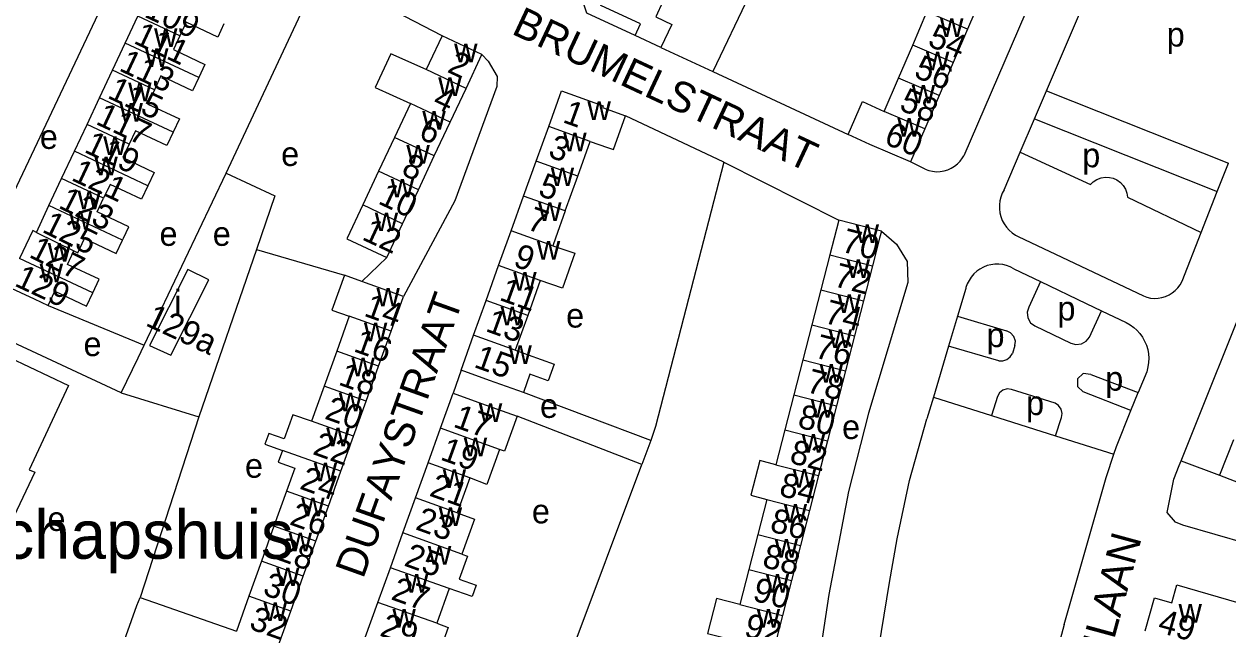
# Model space of a CAD drawing. Extents: x 159045 to 160918, y 380454 to 382516.
# Drawn here: x 160089.8 to 160288.7, y 381185.5 to 381285.4 of the extents above; entities that cross this region are included whole.
import ezdxf

# ---------------------------------------------------------------- set-up
doc = ezdxf.new("R2010")
doc.units = 0
for name, color, linetype in [('BLT_Basislijn', 7, 'Continuous'), ('BLT_Bebouwing', 7, 'Continuous'), ('BLT_Bebouwing_beschrifting', 7, 'Continuous'), ('BLT_Centroide', 7, 'Continuous'), ('BLT_Huisnummer', 7, 'Continuous'), ('BLT_Huisnummer_ tussenligend', 7, 'Continuous'), ('BLT_Onderverdeling_panden', 7, 'Continuous'), ('BLT_Straatnaam', 7, 'Continuous')]:
    doc.layers.add(name, color=color, linetype=linetype)

msp = doc.modelspace()

# ---------------------------------------------------------------- linework, layer by layer
at = {"layer": 'BLT_Basislijn'}
for p, q in [((160263.72, 381306.96), (160245.07, 381263.61)), ((160123.21, 381260.74), (160138.75, 381293.92)), ((160158.88, 381283.41), (160138.75, 381293.92)), ((160258.7, 381274.33), (160266.79, 381293.2)), ((160195.03, 381281.48), (160203.6, 381277.5)), ((160203.6, 381277.5), (160225.95, 381267.13)), ((160256.73, 381269.73), (160258.7, 381274.33)), ((160258.7, 381274.33), (160288.75, 381262.37)), ((160205.39, 381262.57), (160189.18, 381270.21)), ((160254.38, 381264.23), (160256.73, 381269.73)), ((160256.73, 381269.73), (160286.92, 381257.72)), ((160280.94, 381213.21), (160301.87, 381265.58)), ((160251.7, 381257.99), (160254.38, 381264.23)), ((160205.39, 381262.57), (160224.4, 381252.99)), ((160238.67, 381261.38), (160236.26, 381262.58)), ((160286.92, 381257.72), (160288.75, 381262.37)), ((160109.65, 381232.33), (160123.21, 381260.74)), ((160284.26, 381250.96), (160286.92, 381257.72)), ((160254.04, 381250.26), (160274.71, 381240.45)), ((160281.09, 381242.92), (160284.26, 381250.96)), ((160128.23, 381248.12), (160118.69, 381220.46)), ((160128.23, 381248.12), (160142.75, 381243.89)), ((160149.74, 381246.8), (160145.61, 381242.86)), ((160253.32, 381244.96), (160257.74, 381242.83)), ((160245.36, 381241.66), (160244, 381237.11)), ((160257.74, 381242.83), (160255.8, 381238.6)), ((160257.74, 381242.83), (160265.25, 381239.23)), ((160093.82, 381238.87), (160109.65, 381232.33)), ((160265.25, 381239.23), (160267.8, 381237.98)), ((160265.79, 381233.65), (160267.8, 381237.98)), ((160267.8, 381237.98), (160271.88, 381236.05)), ((160105.85, 381224.47), (160078.47, 381237.17)), ((160244, 381237.11), (160242.53, 381232.18)), ((160244, 381237.11), (160252.09, 381234.67)), ((160256.79, 381235.52), (160262.75, 381232.67)), ((160242.53, 381232.18), (160240.03, 381223.75)), ((160250.82, 381229.75), (160242.53, 381232.18)), ((160253.5, 381232.25), (160253.11, 381230.94)), ((160162, 381228.2), (160160.69, 381224.41)), ((160275.26, 381227.94), (160273.84, 381224.49)), ((160266.05, 381227.5), (160273.84, 381224.49)), ((160105.85, 381224.47), (160118.69, 381220.46)), ((160193.33, 381216.6), (160172.3, 381224.5)), ((160240.03, 381223.75), (160238.96, 381220.17)), ((160240.03, 381223.75), (160249.61, 381220.72)), ((160250.6, 381223.83), (160249.61, 381220.72)), ((160260.16, 381222.72), (160252.9, 381225)), ((160272.62, 381221.54), (160264.74, 381224.64)), ((160272.62, 381221.54), (160273.84, 381224.49)), ((160118.69, 381220.46), (160109.03, 381190.62)), ((160191.86, 381212.6), (160171.27, 381220.6)), ((160249.61, 381220.72), (160260.21, 381217.36)), ((160260.21, 381217.36), (160261.17, 381220.4)), ((160193.33, 381216.6), (160191.86, 381212.6)), ((160260.21, 381217.36), (160269.83, 381214.31)), ((160174.48, 381166.13), (160191.86, 381212.6)), ((160280.94, 381213.21), (160287.29, 381210.87)), ((160261.65, 381186.17), (160268.57, 381210.49)), ((160109.03, 381190.62), (160124.89, 381185.09))]:
    msp.add_line(p, q, dxfattribs=at)
for points in [[(160222.72, 381318.67), (160221.61, 381315.23), (160203.6, 381277.5)], [(160116.55, 381305.15), (160111.63, 381307.38), (160081.39, 381243.37)], [(160190.74, 381283.49), (160182.8, 381287.17), (160182.15, 381288.99), (160184.44, 381294.05), (160185.83, 381293.43)], [(160165.46, 381280.32), (160166.51, 381279.22), (160167.97, 381276.71), (160167.94, 381275.05), (160160.97, 381256.17), (160152.52, 381240.38)], [(160238.67, 381261.38), (160239.27, 381261.17), (160239.89, 381261.04), (160240.53, 381260.98), (160241.16, 381261.01), (160241.79, 381261.11), (160242.4, 381261.3), (160242.98, 381261.55), (160243.52, 381261.88), (160244.02, 381262.28), (160244.46, 381262.73), (160244.85, 381263.24), (160245.07, 381263.61)], [(160254.38, 381264.23), (160265.98, 381258.86), (160266.41, 381259.28), (160267, 381259.68), (160267.71, 381259.96), (160268.43, 381260.07), (160269.09, 381260.04), (160269.73, 381259.89), (160270.33, 381259.62), (160270.91, 381259.2), (160271.39, 381258.68), (160271.75, 381258.07), (160271.97, 381257.43), (160272.06, 381256.79), (160284.26, 381250.96)], [(160205.39, 381262.57), (160194.13, 381218.88), (160193.33, 381216.6)], [(160123.21, 381260.74), (160131.26, 381257.01), (160128.23, 381248.12)], [(160251.7, 381257.99), (160251.4, 381257.41), (160251.16, 381256.79), (160251.01, 381256.15), (160250.93, 381255.5), (160250.93, 381254.84), (160251.01, 381254.19), (160251.17, 381253.55), (160251.4, 381252.93), (160251.71, 381252.35), (160252.09, 381251.81), (160252.52, 381251.32), (160253.02, 381250.89), (160253.56, 381250.52), (160254.04, 381250.26)], [(160231.44, 381251.18), (160233.95, 381249), (160235.7, 381246.13), (160235.81, 381242.7), (160229.31, 381221.08), (160226.02, 381208.16), (160222.77, 381191.13), (160220.43, 381175.9)], [(160253.32, 381244.96), (160252.73, 381245.26), (160252.12, 381245.49), (160251.48, 381245.64), (160250.83, 381245.71), (160250.18, 381245.71), (160249.53, 381245.62), (160248.9, 381245.46), (160248.29, 381245.21), (160247.71, 381244.9), (160247.18, 381244.52), (160246.7, 381244.08), (160246.27, 381243.58), (160245.91, 381243.03), (160245.62, 381242.45), (160245.4, 381241.83), (160245.36, 381241.66)], [(160274.71, 381240.45), (160275.3, 381240.24), (160275.91, 381240.11), (160276.53, 381240.05), (160277.16, 381240.08), (160277.77, 381240.18), (160278.37, 381240.37), (160278.94, 381240.62), (160279.47, 381240.95), (160279.96, 381241.35), (160280.39, 381241.8), (160280.76, 381242.3), (160281.09, 381242.92)], [(160255.8, 381238.6), (160255.53, 381237.78), (160255.62, 381236.85), (160256.09, 381236.03), (160256.79, 381235.52)], [(160271.88, 381236.05), (160272.52, 381235.7), (160273.11, 381235.27), (160273.65, 381234.78), (160274.14, 381234.24), (160274.57, 381233.64), (160274.92, 381233.01), (160275.21, 381232.33), (160275.42, 381231.63), (160275.55, 381230.91), (160275.61, 381230.18), (160275.58, 381229.46), (160275.47, 381228.73), (160275.26, 381227.94)], [(160253.5, 381232.25), (160253.56, 381232.99), (160253.31, 381233.76), (160252.77, 381234.36), (160252.09, 381234.67)], [(160262.75, 381232.67), (160263.56, 381232.46), (160264.46, 381232.57), (160265.25, 381233), (160265.79, 381233.65)], [(160105.85, 381224.47), (160108.65, 381230.24), (160109.65, 381232.33)], [(160250.82, 381229.75), (160251.49, 381229.74), (160252.17, 381229.96), (160252.73, 381230.39), (160253.11, 381230.94)], [(160266.05, 381227.5), (160264.78, 381227.64), (160263.83, 381226.79), (160263.81, 381225.52), (160264.74, 381224.64)], [(160252.9, 381225), (160252.22, 381225.09), (160251.51, 381224.89), (160250.93, 381224.43), (160250.6, 381223.83)], [(160261.17, 381220.4), (160261.27, 381221.06), (160261.11, 381221.75), (160260.71, 381222.34), (160260.16, 381222.72)], [(160232.78, 381193.15), (160234.04, 381200.35), (160236.1, 381209.96), (160238.96, 381220.17)], [(160269.83, 381214.31), (160270.25, 381215.58), (160272.62, 381221.54)], [(160268.57, 381210.49), (160268.61, 381210.64), (160269.83, 381214.31)], [(160347.04, 381193.19), (160346.77, 381192.26), (160345.84, 381188.3), (160345.36, 381187.39), (160343.35, 381185.68), (160339.97, 381185.65), (160281.2, 381202.61), (160280.02, 381203.09), (160278.65, 381204.68), (160279.73, 381210.18), (160280.63, 381212.43), (160280.94, 381213.21)], [(160227.8, 381161.01), (160229.62, 381173.91), (160232.78, 381193.15)], [(160105.84, 381174.41), (160103.46, 381175.25), (160108.45, 381189.33), (160109.03, 381190.62)], [(160261.65, 381186.17), (160256.59, 381167.34), (160253.29, 381154.15)]]:
    msp.add_lwpolyline(points, dxfattribs=at)
at = {"layer": 'BLT_Bebouwing'}
for p, q in [((160248.01, 381289.99), (160245.66, 381284.51)), ((160236.61, 381281.9), (160238.96, 381287.38)), ((160106.55, 381282.23), (160108.63, 381286.66)), ((160165.46, 381280.32), (160158.88, 381283.41)), ((160195.03, 381281.48), (160190.74, 381283.49)), ((160245.66, 381284.51), (160243.31, 381279.03)), ((160104.43, 381277.73), (160106.55, 381282.23)), ((160234.25, 381276.42), (160236.61, 381281.9)), ((160162.84, 381274.74), (160165.46, 381280.32)), ((160102.31, 381273.2), (160104.43, 381277.73)), ((160243.31, 381279.03), (160240.96, 381273.54)), ((160231.9, 381270.94), (160234.25, 381276.42)), ((160160.22, 381269.15), (160162.84, 381274.74)), ((160240.96, 381273.54), (160238.61, 381268.06)), ((160100.23, 381268.79), (160102.31, 381273.2)), ((160153.63, 381272.24), (160151.01, 381266.65)), ((160098.15, 381264.35), (160100.23, 381268.79)), ((160157.59, 381263.57), (160160.22, 381269.15)), ((160174.41, 381262.71), (160176.48, 381268.46)), ((160238.61, 381268.06), (160236.26, 381262.58)), ((160151.01, 381266.65), (160148.39, 381261.07)), ((160181.29, 381260.24), (160183.35, 381265.99)), ((160229.55, 381265.46), (160225.95, 381267.13)), ((160236.26, 381262.58), (160229.55, 381265.46)), ((160096.03, 381259.85), (160098.15, 381264.35)), ((160154.97, 381257.98), (160157.59, 381263.57)), ((160172.34, 381256.96), (160174.41, 381262.71)), ((160093.93, 381255.37), (160096.03, 381259.85)), ((160148.39, 381261.07), (160145.77, 381255.48)), ((160179.22, 381254.49), (160181.29, 381260.24)), ((160152.35, 381252.39), (160154.97, 381257.98)), ((160170.27, 381251.21), (160172.34, 381256.96)), ((160091.86, 381250.96), (160093.93, 381255.37)), ((160231.44, 381251.18), (160224.4, 381252.99)), ((160222.92, 381247.22), (160221.43, 381241.45)), ((160116.87, 381244.84), (160110.52, 381232.26)), ((160166.14, 381239.7), (160168.21, 381245.46)), ((160229.95, 381245.41), (160228.47, 381239.64)), ((160152.52, 381240.38), (160145.61, 381242.86)), ((160175.08, 381242.98), (160173.02, 381237.23)), ((160150.45, 381234.61), (160152.52, 381240.38)), ((160164.07, 381233.95), (160166.14, 381239.7)), ((160221.43, 381241.45), (160219.95, 381235.68)), ((160228.47, 381239.64), (160226.98, 381233.86)), ((160143.54, 381237.09), (160141.47, 381231.31)), ((160173.02, 381237.23), (160170.95, 381231.48)), ((160219.95, 381235.68), (160218.46, 381229.9)), ((160148.38, 381228.83), (160150.45, 381234.61)), ((160162, 381228.2), (160164.07, 381233.95)), ((160226.98, 381233.86), (160225.5, 381228.09)), ((160141.47, 381231.31), (160139.4, 381225.53)), ((160218.46, 381229.9), (160216.98, 381224.13)), ((160146.31, 381223.05), (160148.38, 381228.83)), ((160225.5, 381228.09), (160224.01, 381222.32)), ((160139.4, 381225.53), (160137.32, 381219.76)), ((160158.62, 381218.64), (160160.69, 381224.41)), ((160216.98, 381224.13), (160215.49, 381218.36)), ((160144.24, 381217.28), (160146.31, 381223.05)), ((160224.01, 381222.32), (160222.53, 381216.55)), ((160156.55, 381212.87), (160158.62, 381218.64)), ((160215.49, 381218.36), (160214.01, 381212.58)), ((160142.16, 381211.5), (160144.24, 381217.28)), ((160222.53, 381216.55), (160221.04, 381210.77)), ((160289.58, 381216.69), (160287.29, 381210.87)), ((160154.47, 381207.11), (160156.55, 381212.87)), ((160140.09, 381205.72), (160142.16, 381211.5)), ((160163.46, 381210.39), (160161.38, 381204.62)), ((160221.04, 381210.77), (160219.56, 381205)), ((160287.29, 381210.87), (160294.59, 381208)), ((160133.18, 381208.2), (160131.1, 381202.43)), ((160152.4, 381201.34), (160154.47, 381207.11)), ((160212.52, 381206.81), (160211.04, 381201.04)), ((160138.02, 381199.95), (160140.09, 381205.72)), ((160219.56, 381205), (160218.07, 381199.23)), ((160131.1, 381202.43), (160129.03, 381196.65)), ((160135.94, 381194.17), (160138.02, 381199.95)), ((160150.33, 381195.57), (160152.4, 381201.34)), ((160211.04, 381201.04), (160209.55, 381195.26)), ((160218.07, 381199.23), (160216.59, 381193.46)), ((160129.03, 381196.65), (160126.96, 381190.87)), ((160133.87, 381188.39), (160135.94, 381194.17)), ((160148.25, 381189.8), (160150.33, 381195.57)), ((160209.55, 381195.26), (160208.07, 381189.49)), ((160160.05, 381192.13), (160157.99, 381186.4)), ((160216.59, 381193.46), (160215.1, 381187.68)), ((160126.96, 381190.87), (160124.89, 381185.09)), ((160131.8, 381182.61), (160133.87, 381188.39)), ((160146.18, 381184.04), (160148.25, 381189.8)), ((160215.1, 381187.68), (160213.02, 381179.58))]:
    msp.add_line(p, q, dxfattribs=at)
for points in [[(160190.74, 381283.49), (160191.63, 381285.4), (160185.1, 381288.45), (160187.14, 381292.82)], [(160194.9, 381289.29), (160195.35, 381289.08), (160194.16, 381286.55), (160196.82, 381285.31), (160195.03, 381281.48)], [(160122.85, 381285.38), (160121.83, 381283.21), (160116.61, 381285.66), (160115.55, 381283.41)], [(160115.55, 381283.41), (160114.49, 381281.16), (160119.7, 381278.71), (160118.67, 381276.53)], [(160158.88, 381283.41), (160156.75, 381278.89), (160156.26, 381277.83)], [(160156.26, 381277.83), (160150.41, 381280.44), (160147.82, 381274.91), (160153.63, 381272.24)], [(160118.67, 381276.53), (160117.65, 381274.35), (160112.44, 381276.8), (160111.35, 381274.48)], [(160111.35, 381274.48), (160110.26, 381272.15), (160115.48, 381269.7), (160114.44, 381267.5)], [(160176.48, 381268.46), (160178.6, 381274.36), (160185.47, 381271.88), (160185.36, 381271.58), (160189.18, 381270.21)], [(160225.95, 381267.13), (160228.29, 381272.58), (160231.9, 381270.94)], [(160183.35, 381265.99), (160186.18, 381264.97), (160187.17, 381264.62), (160189.18, 381270.21)], [(160114.44, 381267.5), (160113.41, 381265.3), (160108.22, 381267.74), (160107.18, 381265.52)], [(160107.18, 381265.52), (160106.14, 381263.31), (160111.34, 381260.87), (160110.29, 381258.65)], [(160110.29, 381258.65), (160109.25, 381256.42), (160104.03, 381258.87), (160102.96, 381256.59)], [(160106.09, 381249.67), (160106.19, 381249.88), (160106.25, 381250), (160107.12, 381251.86), (160101.9, 381254.32), (160102.96, 381256.59)], [(160145.77, 381255.48), (160143.2, 381250), (160143.14, 381249.88), (160149.74, 381246.8)], [(160179.22, 381254.49), (160177.61, 381250), (160177.15, 381248.73)], [(160149.74, 381246.8), (160151.23, 381250), (160152.35, 381252.39)], [(160224.4, 381252.99), (160223.64, 381250), (160222.92, 381247.22)], [(160091.86, 381250.96), (160091.25, 381251.25), (160090.67, 381250), (160089.1, 381246.64)], [(160098.06, 381247.89), (160098.73, 381247.57), (160099.82, 381249.92), (160105.06, 381247.47), (160106.09, 381249.67)], [(160168.21, 381245.46), (160169.84, 381250), (160170.27, 381251.21)], [(160231.44, 381251.18), (160231.13, 381250), (160229.95, 381245.41)], [(160101.19, 381240.99), (160102.23, 381243.22), (160097.02, 381245.66), (160098.06, 381247.89)], [(160177.15, 381248.73), (160180.82, 381247.5), (160178.75, 381241.75), (160175.08, 381242.98)], [(160110.52, 381232.26), (160114.07, 381230.68), (160120.33, 381243.1), (160116.87, 381244.84)], [(160142.75, 381243.89), (160140.68, 381238.11), (160143.54, 381237.09)], [(160145.61, 381242.86), (160142.75, 381243.89)], [(160086.97, 381242.07), (160091.5, 381239.96), (160093.82, 381238.87)], [(160093.82, 381238.87), (160094.91, 381241.22), (160100.15, 381238.77), (160101.19, 381240.99)], [(160170.95, 381231.48), (160177.36, 381229.2), (160176.37, 381226.44), (160173.38, 381227.51), (160172.3, 381224.5)], [(160172.3, 381224.5), (160166.71, 381226.51), (160162, 381228.2)], [(160160.69, 381224.41), (160165.4, 381222.71), (160171.27, 381220.6)], [(160137.32, 381219.76), (160134.24, 381220.82), (160132.81, 381216.85), (160130.26, 381217.76), (160129.62, 381216), (160132.53, 381214.95)], [(160171.27, 381220.6), (160169.19, 381214.81), (160168.36, 381215.09)], [(160132.53, 381214.95), (160131.82, 381212.98), (160134.54, 381212), (160133.18, 381208.2)], [(160168.36, 381215.09), (160166.28, 381209.3), (160163.46, 381210.39)], [(160214.01, 381212.58), (160211.34, 381213.3), (160209.86, 381207.55), (160212.52, 381206.81)], [(160161.38, 381204.62), (160164.23, 381203.61), (160162.15, 381197.83)], [(160162.15, 381197.83), (160163.07, 381197.5), (160161.69, 381193.67), (160164.51, 381192.68), (160163.84, 381190.79), (160160.05, 381192.13)], [(160275, 381185.12), (160276.52, 381190.57), (160279.38, 381189.78), (160280.23, 381192.74), (160290.49, 381189.76)], [(160208.07, 381189.49), (160204.21, 381190.48), (160202.72, 381184.71), (160206.65, 381183.69), (160206.14, 381181.69), (160208.45, 381180.98)], [(160157.99, 381186.4), (160159.89, 381185.71), (160158.66, 381182.31), (160161.84, 381181.17), (160160.99, 381178.78), (160158.83, 381179.55)]]:
    msp.add_lwpolyline(points, dxfattribs=at)
msp.add_lwpolyline([(160084.11, 381231.82), (160097.17, 381225.65), (160090.69, 381211.76), (160091.6, 381211.33), (160088.14, 381204.01), (160087.27, 381204.36), (160080.55, 381190.6), (160067.54, 381196.84), (160069.83, 381201.63), (160072.09, 381200.56), (160076.37, 381209.66), (160073.54, 381211.02), (160076.95, 381218.25), (160079.83, 381216.89), (160084.08, 381225.98), (160081.87, 381227.05)], close=True, dxfattribs=at)
at = {"layer": 'BLT_Onderverdeling_panden'}
for p, q in [((160245.66, 381284.51), (160238.96, 381287.38)), ((160115.55, 381283.41), (160108.63, 381286.66)), ((160118.67, 381276.53), (160106.55, 381282.23)), ((160243.31, 381279.03), (160236.61, 381281.9)), ((160111.35, 381274.48), (160104.43, 381277.73)), ((160162.84, 381274.74), (160156.26, 381277.83)), ((160240.96, 381273.54), (160234.25, 381276.42)), ((160114.44, 381267.5), (160102.31, 381273.2)), ((160160.22, 381269.15), (160153.63, 381272.24)), ((160238.61, 381268.06), (160231.9, 381270.94)), ((160107.18, 381265.52), (160100.23, 381268.79)), ((160183.35, 381265.99), (160176.48, 381268.46)), ((160157.59, 381263.57), (160151.01, 381266.65)), ((160110.29, 381258.65), (160098.15, 381264.35)), ((160181.29, 381260.24), (160174.41, 381262.71)), ((160102.96, 381256.59), (160096.03, 381259.85)), ((160154.97, 381257.98), (160148.39, 381261.07)), ((160179.22, 381254.49), (160172.34, 381256.96)), ((160106.09, 381249.67), (160093.93, 381255.37)), ((160152.35, 381252.39), (160145.77, 381255.48)), ((160091.86, 381250.96), (160098.06, 381247.89)), ((160177.15, 381248.73), (160170.27, 381251.21)), ((160101.19, 381240.99), (160089.1, 381246.64)), ((160222.92, 381247.22), (160229.95, 381245.41)), ((160175.08, 381242.98), (160168.21, 381245.46)), ((160173.02, 381237.23), (160166.14, 381239.7)), ((160221.43, 381241.45), (160228.47, 381239.64)), ((160150.45, 381234.61), (160143.54, 381237.09)), ((160219.95, 381235.68), (160226.98, 381233.86)), ((160170.95, 381231.48), (160164.07, 381233.95)), ((160148.38, 381228.83), (160141.47, 381231.31)), ((160218.46, 381229.9), (160225.5, 381228.09)), ((160146.31, 381223.05), (160139.4, 381225.53)), ((160216.98, 381224.13), (160224.01, 381222.32)), ((160144.24, 381217.28), (160137.32, 381219.76)), ((160168.36, 381215.09), (160158.62, 381218.64)), ((160215.49, 381218.36), (160222.53, 381216.55)), ((160142.16, 381211.5), (160132.53, 381214.95)), ((160163.46, 381210.39), (160156.55, 381212.87)), ((160214.01, 381212.58), (160221.04, 381210.77)), ((160140.09, 381205.72), (160133.18, 381208.2)), ((160161.38, 381204.62), (160154.47, 381207.11)), ((160212.52, 381206.81), (160219.56, 381205)), ((160138.02, 381199.95), (160131.1, 381202.43)), ((160162.15, 381197.83), (160152.4, 381201.34)), ((160211.04, 381201.04), (160218.07, 381199.23)), ((160135.94, 381194.17), (160129.03, 381196.65)), ((160160.05, 381192.13), (160150.33, 381195.57)), ((160209.55, 381195.26), (160216.59, 381193.46)), ((160133.87, 381188.39), (160126.96, 381190.87)), ((160157.99, 381186.4), (160148.25, 381189.8)), ((160208.07, 381189.49), (160215.1, 381187.68))]:
    msp.add_line(p, q, dxfattribs=at)

# ---------------------------------------------------------------- texts
at = {"layer": 'BLT_Bebouwing_beschrifting'}
msp.add_text('Gemeenschapshuis', height=8, dxfattribs=at).set_placement((160039.76, 381197.05))
at = {"layer": 'BLT_Centroide'}
for s, p in [('w', (160241.12, 381283.22)), ('w', (160111.3, 381281.59)), ('p', (160278.56, 381281.65)), ('w', (160160.86, 381279.06)), ('w', (160109.81, 381278.28)), ('w', (160238.78, 381277.72)), ('w', (160107.02, 381272.62)), ('w', (160158.23, 381273.5)), ('w', (160236.44, 381272.25)), ('w', (160105.59, 381269.25)), ('w', (160182.88, 381269.5)), ('w', (160155.61, 381267.91)), ('w', (160234.08, 381266.75)), ('e', (160092.43, 381264.74)), ('w', (160102.91, 381263.72)), ('w', (160178.88, 381264.34)), ('e', (160132.29, 381261.92)), ('w', (160152.98, 381262.31)), ('p', (160264.61, 381261.71)), ('w', (160101.44, 381260.38)), ('w', (160176.82, 381258.59)), ('w', (160150.38, 381256.72)), ('w', (160098.66, 381254.75)), ('w', (160174.74, 381252.84)), ('w', (160097.22, 381251.41)), ('w', (160147.75, 381251.16)), ('e', (160112.2, 381248.73)), ('e', (160120.99, 381248.73)), ('w', (160227.17, 381249.19)), ('w', (160093.73, 381246.12)), ('w', (160174.52, 381246.47)), ('w', (160092.4, 381242.72)), ('w', (160225.69, 381243.44)), ('w', (160170.62, 381241.34)), ('i', (160114.62, 381237.42)), ('w', (160148.03, 381238.72)), ('w', (160224.2, 381237.66)), ('w', (160168.54, 381235.59)), ('e', (160179.36, 381235.23)), ('p', (160260.51, 381236.41)), ('w', (160145.96, 381232.97)), ('e', (160099.65, 381230.52)), ('w', (160222.72, 381231.88)), ('p', (160248.8, 381232)), ('w', (160169.83, 381229.22)), ('w', (160143.89, 381227.19)), ('w', (160221.23, 381226.12)), ('p', (160268.41, 381224.81)), ('w', (160141.81, 381221.41)), ('p', (160255.34, 381220.78)), ('w', (160164.94, 381219.62)), ('e', (160175.05, 381220.31)), ('w', (160219.75, 381220.34)), ('e', (160224.94, 381216.82)), ('w', (160139.74, 381215.62)), ('w', (160162.45, 381213.97)), ('w', (160218.27, 381214.56)), ('e', (160126.32, 381210.43)), ('w', (160137.67, 381209.84)), ('w', (160158.97, 381208.75)), ('w', (160216.78, 381208.78)), ('w', (160135.6, 381204.06)), ('e', (160173.71, 381202.89)), ('w', (160215.3, 381203.03)), ('e', (160093.69, 381201.64)), ('w', (160158.32, 381202.47)), ('w', (160133.52, 381198.28)), ('w', (160213.81, 381197.25)), ('w', (160156.52, 381196.06)), ('w', (160131.45, 381192.53)), ('w', (160152.74, 381191.44)), ('w', (160212.33, 381191.47)), ('w', (160129.38, 381186.75)), ('w', (160150.67, 381185.69)), ('w', (160210.84, 381185.69)), ('w', (160280.51, 381186.5))]:
    msp.add_text(s, height=4, dxfattribs=at).set_placement(p)
at = {"layer": 'BLT_Huisnummer'}
for s, rotation, p in [('54', 336.788, (160238.89, 381281.85)), ('111', 334.83, (160107.75, 381282.27)), ('2', 334.8689, (160159.56, 381277.51)), ('115', 334.8299, (160103.43, 381273.24)), ('1', 340.2259, (160178.63, 381269.19)), ('6', 334.8685, (160154.8, 381266.6)), ('60', 336.788, (160231.68, 381265.69)), ('119', 334.8602, (160099.58, 381264.28)), ('5', 340.2212, (160174.54, 381257.12)), ('123', 333.6163, (160095.34, 381255.09)), ('12', 334.9841, (160145.47, 381249.84)), ('70', 345.5677, (160224.65, 381247.82)), ('9', 340.2259, (160170.44, 381245.44)), ('129', 334.9672, (160088.07, 381242.2)), ('14', 340.2648, (160145.79, 381237.22)), ('74', 345.5677, (160221.81, 381236.05)), ('129a', 335.1307, (160109.72, 381235.64)), ('15', 340.2261, (160163.96, 381228.75)), ('18', 340.2648, (160141.59, 381225.85)), ('78', 345.5677, (160218.86, 381224.63)), ('17', 340.2234, (160160.54, 381218.9)), ('22', 340.2622, (160137.34, 381214.37)), ('82', 345.5677, (160216.09, 381212.93)), ('21', 340.2281, (160156.59, 381207.51)), ('26', 340.2622, (160133.51, 381202.76)), ('86', 345.5677, (160212.85, 381201.6)), ('25', 340.2244, (160152.41, 381195.96)), ('32', 340.2568, (160126.82, 381185.54)), ('92', 345.5802, (160208.58, 381184.24)), ('49', 344.4851, (160276.9, 381184.96))]:
    msp.add_text(s, height=4, rotation=rotation, dxfattribs=at).set_placement(p)
at = {"layer": 'BLT_Huisnummer_ tussenligend'}
for s, rotation, p in [('109', 334.8352, (160109.49, 381286.65)), ('113', 334.83, (160105.34, 381277.75)), ('56', 336.788, (160236.61, 381276.71)), ('4', 334.8689, (160157.12, 381271.8)), ('58', 336.788, (160234.19, 381271.28)), ('117', 334.8299, (160101.49, 381268.92)), ('3', 340.2259, (160176.21, 381263.48)), ('8', 334.8685, (160151.95, 381260.6)), ('121', 334.8602, (160097.45, 381259.64)), ('10', 334.8685, (160148.12, 381255.78)), ('125', 333.6163, (160092.63, 381251.09)), ('7', 340.2212, (160172.67, 381251.55)), ('127', 333.6163, (160090.47, 381246.95)), ('72', 345.5677, (160223.38, 381242.11)), ('11', 340.2259, (160168.16, 381239.83)), ('13', 340.2259, (160165.88, 381234.69)), ('16', 340.2648, (160144.08, 381231.36)), ('76', 345.5677, (160220.24, 381230.33)), ('20', 340.2648, (160139.31, 381220.23)), ('80', 345.5677, (160217.43, 381218.78)), ('19', 340.2234, (160158.41, 381213.47)), ('24', 340.2622, (160135.18, 381208.66)), ('84', 345.5677, (160214.37, 381207.51)), ('23', 340.2281, (160154.31, 381201.95)), ('28', 340.2622, (160131.23, 381197.04)), ('88', 345.5677, (160211.58, 381195.74)), ('30', 340.2622, (160129.08, 381191.18)), ('27', 340.2244, (160150.26, 381190.39)), ('90', 345.5677, (160210, 381190.17)), ('29', 340.2244, (160148.41, 381184.39))]:
    msp.add_text(s, height=4, rotation=rotation, dxfattribs=at).set_placement(p)
at = {"layer": 'BLT_Straatnaam'}
for s, height, rotation, p in [('BRUMELSTRAAT', 5, 334.9111, (160170.16, 381283.83)), ('DUFAYSTRAAT', 4.9999, 70.2772, (160145.83, 381193.6)), ('VAN BEETHOVENLAAN', 5, 74.7965, (160254.97, 381128.76))]:
    msp.add_text(s, height=height, rotation=rotation, dxfattribs=at).set_placement(p)

doc.saveas('drawing.dxf')
